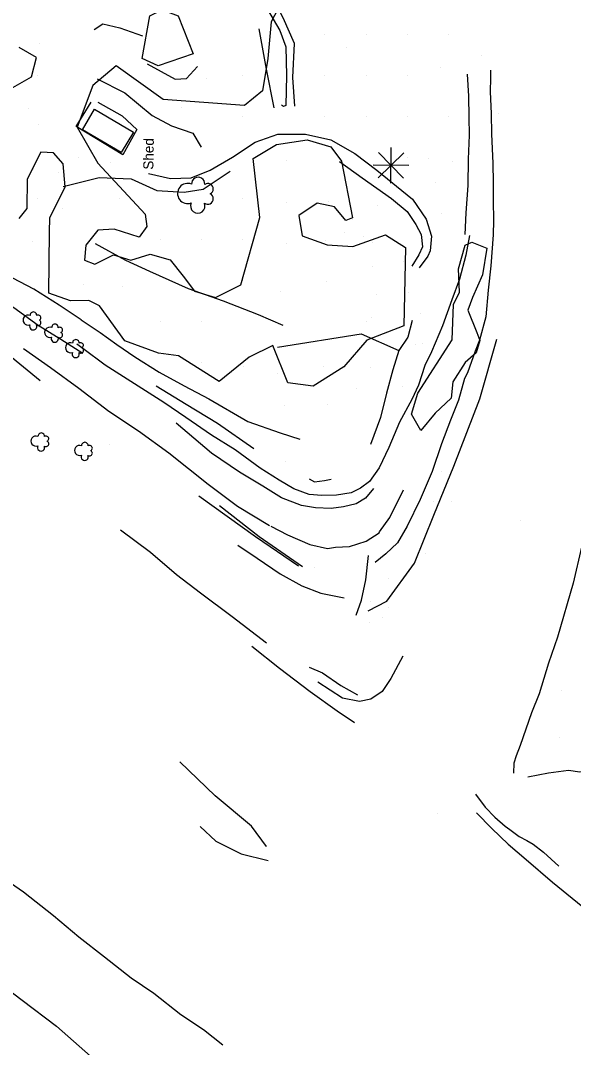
# Model space of a CAD drawing. Extents: x 19528164 to 19545171, y 7585743 to 7602745.
# Drawn here: x 19532177 to 19532446, y 7589871 to 7590372 of the extents above; entities that cross this region are included whole.
import ezdxf

# ---------------------------------------------------------------- set-up
doc = ezdxf.new("R2010")
doc.units = 0
for name, color, linetype in [('PhoBreakLine', 7, 'Continuous'), ('PhoBuilding', 7, 'Continuous'), ('PhoConcreteSlab', 7, 'Continuous'), ('PhoISAEPoints', 7, 'Continuous'), ('PhoNotesDesign', 7, 'Continuous'), ('PhoVegetation', 7, 'Continuous'), ('SurNaturalCells', 7, 'Continuous')]:
    doc.layers.add(name, color=color, linetype=linetype)

# ---------------------------------------------------------------- blocks, each defined once
blk = doc.blocks.new('TRDC')
at = {"layer": 'PhoVegetation'}
for centre, radius, start, end in [((-6, -1.1), 3.52, 65.4824, 294.5175), ((0.1, 4), 4.92, 338.2051, 201.7949), ((4.9, -1.1), 3.21, 265.9982, 94.0018), ((-2.4, -5.9), 2.68, 142.7501, 335.3223), ((2.5, -5.8), 2.67, 206.5242, 35.4033)]:
    blk.add_arc(centre, radius, start, end, dxfattribs=at)

msp = doc.modelspace()

# ---------------------------------------------------------------- linework, layer by layer
at = {"layer": 'PhoBreakLine'}
for points in [[(19532310.39, 7590329.98), (19532309.35, 7590344.06), (19532310.11, 7590360.5), (19532304.61, 7590373.08), (19532299.72, 7590382.39), (19532298.65, 7590391.57), (19532295.72, 7590394.62), (19532287.91, 7590398.6)], [(19532288.27, 7590393.6), (19532293.08, 7590389.87), (19532295.51, 7590383.77), (19532297.08, 7590377.09), (19532302.98, 7590366.85), (19532305.87, 7590359.01), (19532306.27, 7590344.88), (19532305.94, 7590330.27), (19532304.87, 7590329.92), (19532303.89, 7590330.48)], [(19531952.11, 7590377.89), (19531963.88, 7590371.42), (19531980.15, 7590359.08), (19531999.76, 7590345.93), (19532028.04, 7590328.79), (19532041.73, 7590318.4), (19532058.28, 7590306.88), (19532078.33, 7590292.93), (19532101.08, 7590277.81), (19532127.97, 7590259.07), (19532139.92, 7590252.05), (19532145.93, 7590249.55), (19532156.87, 7590241.46), (19532173.4, 7590231.88), (19532185.29, 7590223.17), (19532196.32, 7590216.45), (19532207.14, 7590209.52)], [(19532206.29, 7590225.89), (19532195.53, 7590233.02), (19532183.27, 7590240.78), (19532165.94, 7590249.69), (19532156.57, 7590255.2), (19532143.79, 7590261.17), (19532136.29, 7590268.64), (19532127.31, 7590273.77), (19532121.44, 7590279.07), (19532114.67, 7590283.35), (19532100.93, 7590291.18), (19532088.46, 7590299.14), (19532077.79, 7590306.95), (19532068.4, 7590313.63), (19532060.03, 7590319.64), (19532049.41, 7590325.62), (19532039.33, 7590332.99), (19532028.79, 7590340.47), (19532018.38, 7590349.36), (19532006.17, 7590358.14), (19531996.03, 7590365.75), (19531986.71, 7590372.87)], [(19532212.6, 7590367.34), (19532216.78, 7590370.08), (19532225.16, 7590368.28), (19532236.11, 7590364.37)], [(19532292.76, 7590367.65), (19532296.39, 7590348.02), (19532300.02, 7590329.24)], [(19532238.38, 7590350.63), (19532251.97, 7590343.19), (19532257.5, 7590343.55), (19532262.89, 7590349.29)], [(19532405.59, 7590347.54), (19532405.64, 7590343.9), (19532405.4, 7590336.97), (19532405.88, 7590326.38), (19532406.07, 7590316.34), (19532406.74, 7590302.26), (19532406.86, 7590292.57), (19532406.89, 7590284), (19532407.11, 7590274.27), (19532406.84, 7590267.32), (19532405.78, 7590252.1), (19532404.4, 7590240.37), (19532403.25, 7590227.29), (19532400.24, 7590215.93), (19532398.17, 7590210.58), (19532394.4, 7590200.02), (19532392.92, 7590197.29), (19532390.04, 7590186.74), (19532386.16, 7590176.95), (19532381.78, 7590165.36), (19532377.24, 7590151.87), (19532371.31, 7590138.22), (19532364.94, 7590125.18), (19532360.29, 7590117.08), (19532354.59, 7590111.78), (19532349.45, 7590107.53)], [(19532213.99, 7590343.3), (19532227.54, 7590336.47), (19532240.84, 7590325.39), (19532250.26, 7590320.41), (19532260.56, 7590316.89), (19532264.62, 7590310.08)], [(19532393.3, 7590267.39), (19532393.81, 7590277.95), (19532394.67, 7590291.33), (19532394.92, 7590304.11), (19532395.33, 7590315.93), (19532395.22, 7590324.68), (19532395.04, 7590334.84), (19532394.4, 7590345.65)], [(19532214.3, 7590332.01), (19532226.24, 7590325.28), (19532233.32, 7590318.62), (19532226.62, 7590306.36), (19532203.76, 7590320.1), (19532211.15, 7590331.94)], [(19532239.11, 7590297.2), (19532249.76, 7590294.81), (19532259.89, 7590295.05), (19532269.07, 7590298.83), (19532279.95, 7590305.11), (19532290.94, 7590312.38), (19532301.97, 7590316.33), (19532315.55, 7590316.4), (19532327.9, 7590313.58), (19532339.6, 7590306.93), (19532350.21, 7590298.78), (19532367.55, 7590284.75), (19532374.2, 7590274.98), (19532376.93, 7590266.58), (19532376.26, 7590259.54), (19532375.03, 7590256.82), (19532370.91, 7590251.13)], [(19532332.07, 7590303.06), (19532343.08, 7590295.05), (19532357.45, 7590285.03), (19532364.99, 7590278.66), (19532369.31, 7590272.26), (19532371.91, 7590267.41), (19532372.45, 7590261.45), (19532370.69, 7590257.61), (19532367.34, 7590251.96)], [(19532230.68, 7590294.57), (19532243.12, 7590288.95), (19532256.48, 7590288.07), (19532265.74, 7590289.47), (19532278.77, 7590298.38)], [(19532197.55, 7590290.83), (19532215.04, 7590295.29), (19532230.68, 7590294.57)], [(19532395.3, 7590266.96), (19532393.52, 7590257.31), (19532390.45, 7590245.72), (19532386.82, 7590235.67), (19532382.27, 7590222.85), (19532376.82, 7590210.32), (19532373.65, 7590203.61), (19532370.47, 7590194.04), (19532367.33, 7590186.93), (19532361.23, 7590175.91), (19532356.11, 7590163.68), (19532351.43, 7590153.77), (19532346.6, 7590147.02), (19532342.3, 7590143.7), (19532337.72, 7590141.47), (19532330.55, 7590140.31), (19532323.49, 7590140.15), (19532317.27, 7590140.61), (19532309.78, 7590143.53), (19532302.68, 7590147.66), (19532293.45, 7590153.52), (19532281.28, 7590162.39), (19532269.75, 7590169.59), (19532257.27, 7590178.17), (19532246.5, 7590185.51), (19532232.21, 7590194.72), (19532217.99, 7590203.76), (19532207.1, 7590211.86), (19532204.18, 7590213.9)], [(19532213.04, 7590263.05), (19532227.8, 7590254.88), (19532239.57, 7590249.55), (19532258.32, 7590241.11), (19532275.46, 7590235.1), (19532292.51, 7590228.47), (19532304.48, 7590223.29)], [(19532471.34, 7590252.36), (19532473.07, 7590240.9), (19532472.99, 7590225.89), (19532471.86, 7590210.37), (19532469.14, 7590193.18), (19532465.68, 7590174.46), (19532462.79, 7590158.1), (19532455.11, 7590131.24), (19532449.95, 7590114.96), (19532445.84, 7590097.49), (19532438.24, 7590071.21), (19532433.84, 7590058.48), (19532431.63, 7590050.93), (19532429.34, 7590043.46), (19532425.56, 7590034.27), (19532419.98, 7590018.25), (19532418.04, 7590013.36), (19532417.02, 7590009.67), (19532416.83, 7590004.81)], [(19532131.78, 7590239.08), (19532155.46, 7590221.38), (19532186.32, 7590196.34)], [(19532206.29, 7590225.89), (19532215.53, 7590219.69), (19532223.6, 7590213.89), (19532232.47, 7590207.87), (19532244.25, 7590200.41), (19532256.5, 7590193.6), (19532268.51, 7590187.35), (19532287.5, 7590176.36), (19532303.1, 7590170.78), (19532312.7, 7590167.7)], [(19532367.46, 7590225.6), (19532365.42, 7590217.4), (19532360.97, 7590210.96), (19532357.98, 7590201.42), (19532354.89, 7590190.03), (19532352.03, 7590178.22), (19532347.23, 7590165.08)], [(19532301.87, 7590212.56), (19532342.65, 7590219.02), (19532360.97, 7590210.96)], [(19532178.16, 7590211.87), (19532191.31, 7590202.56), (19532205.19, 7590192.55), (19532219.75, 7590181.32), (19532234.16, 7590171.76), (19532248.98, 7590160.95), (19532268.18, 7590145.7), (19532282.47, 7590135.07), (19532297.93, 7590125.5)], [(19532346.1, 7590083.95), (19532355.16, 7590088.64), (19532368.54, 7590107.25), (19532378.03, 7590130.54), (19532387.74, 7590154.46), (19532400.44, 7590187.4), (19532408.74, 7590216.36)], [(19532242.74, 7590193.61), (19532257.37, 7590184.68), (19532272.73, 7590175.41), (19532290.31, 7590163.09)], [(19532348.69, 7590143.59), (19532344.74, 7590138.98), (19532340.24, 7590136.06), (19532334, 7590134.61), (19532328.03, 7590133.89), (19532320.43, 7590134.18), (19532313.61, 7590135.38), (19532303.86, 7590139.08), (19532294.65, 7590144.68), (19532283.3, 7590151.64), (19532269.68, 7590160.86), (19532252.54, 7590175.4)], [(19532317.27, 7590148.37), (19532319.81, 7590146.81), (19532324.69, 7590147.44), (19532328.01, 7590148.21)], [(19532298.55, 7590125.23), (19532306.74, 7590121.05), (19532317.61, 7590116.34), (19532326.2, 7590114.42), (19532330.05, 7590115.09), (19532336.89, 7590115.28), (19532345.02, 7590117.91), (19532351.46, 7590122), (19532351.62, 7590122.55), (19532356.53, 7590129.42), (19532363.17, 7590142.96)], [(19532312.05, 7590105.69), (19532291.17, 7590120.12), (19532263.58, 7590139.95)], [(19532314.05, 7590105.39), (19532292.88, 7590120.11), (19532273.7, 7590135.15)], [(19532225.4, 7590123.51), (19532240, 7590112.62), (19532252.68, 7590101.68), (19532264.36, 7590092.76), (19532279.75, 7590081.24), (19532296.48, 7590068.31)], [(19532282.56, 7590116.07), (19532291.89, 7590109.69), (19532303.13, 7590102.08), (19532313.77, 7590096.15), (19532323.01, 7590092.52), (19532334.38, 7590090.38)], [(19532340.23, 7590081.81), (19532342.8, 7590089.23), (19532344.87, 7590099.07), (19532346.12, 7590110.99)], [(19531943.66, 7590093.23), (19531956.95, 7590083.75), (19531973.48, 7590072.16), (19531986.18, 7590061.94), (19531997.32, 7590054.52), (19532003.54, 7590049.96), (19532012.67, 7590041.24), (19532027.38, 7590026.9), (19532038.35, 7590015.15), (19532049.39, 7590006.69), (19532058.68, 7589999.2), (19532065.06, 7589990.64), (19532074.56, 7589979.59), (19532089.81, 7589967.19), (19532103.84, 7589955.23), (19532121.49, 7589938.61), (19532138.11, 7589923.71), (19532161.1, 7589906.46), (19532177.61, 7589894.18), (19532194.23, 7589881.57), (19532216.34, 7589861.94), (19532233.39, 7589846.76), (19532248.3, 7589832.75)], [(19532289.35, 7590066.7), (19532302.87, 7590056.09), (19532317.72, 7590044.64), (19532330.85, 7590035.19), (19532339.29, 7590029.61)], [(19532362.88, 7590061.95), (19532357.05, 7590050.92), (19532352.82, 7590044.71), (19532347.4, 7590040.91), (19532341.74, 7590039.75), (19532333.49, 7590041.36), (19532321.56, 7590049.18)], [(19532317.24, 7590056.48), (19532323.83, 7590053.77), (19532332.73, 7590047.58), (19532340.89, 7590043.05)], [(19532296.55, 7589969.02), (19532296.53, 7589969.09), (19532289.22, 7589978.93), (19532271.44, 7589993.73), (19532254.37, 7590010.31)], [(19532423.81, 7590003.1), (19532433.91, 7590005.02), (19532443.57, 7590006.27), (19532449.06, 7590005.46), (19532456.93, 7590006.98), (19532464.94, 7590008.3), (19532469.91, 7590009.48)], [(19532398.36, 7589994.57), (19532403.03, 7589988.26), (19532407.75, 7589983.39), (19532412.7, 7589978.96), (19532415.02, 7589977.33), (19532419.5, 7589974.01), (19532423.21, 7589972.07), (19532426.4, 7589970.29), (19532431.41, 7589966.27), (19532438.88, 7589959.53)], [(19532398.73, 7589985.55), (19532406.3, 7589977.89), (19532414.23, 7589970.19), (19532422.89, 7589962.79), (19532435.76, 7589951.77), (19532448.03, 7589941.8), (19532460.66, 7589931.47), (19532474.55, 7589920.17), (19532492.54, 7589904.91), (19532510.78, 7589889.47), (19532532.24, 7589872.05), (19532549.74, 7589859.48), (19532570.76, 7589842.62), (19532589.33, 7589827.72), (19532610.19, 7589811.03), (19532628.19, 7589795.74), (19532654.79, 7589774.06), (19532674.84, 7589758.75), (19532701.07, 7589737.17), (19532717.49, 7589723.97)], [(19532264.17, 7589978.88), (19532271.91, 7589971.73), (19532284.22, 7589965.54), (19532297.3, 7589962.3)], [(19532275.33, 7589872.22), (19532265.81, 7589879.73), (19532254.82, 7589887.09), (19532241.57, 7589897.37), (19532230.6, 7589904.88), (19532217.68, 7589915.18), (19532205.06, 7589924.82), (19532192.85, 7589935.31), (19532178.19, 7589946.82), (19532167.66, 7589954.09)]]:
    msp.add_lwpolyline(points, dxfattribs=at)
at = {"layer": 'PhoBuilding'}
msp.add_lwpolyline([(19532212.7, 7590328.5), (19532231.67, 7590317.36), (19532225.82, 7590307.38), (19532206.84, 7590318.52)], close=True, dxfattribs=at)
at = {"layer": 'PhoConcreteSlab'}
msp.add_lwpolyline([(19532239.7, 7590374), (19532245.71, 7590377.02), (19532253.56, 7590374), (19532260.84, 7590355.52), (19532243.84, 7590349.74), (19532236.01, 7590353.17)], close=True, dxfattribs=at)
at = {"layer": 'PhoISAEPoints'}
for p, q in [((19532325, 7590365), (19532325, 7590365)), ((19532345, 7590365), (19532345, 7590365)), ((19532365, 7590365), (19532365, 7590365)), ((19532385, 7590365), (19532385, 7590365)), ((19532186.21, 7590360.75), (19532186.21, 7590360.75)), ((19532335.35, 7590358.75), (19532335.35, 7590358.75)), ((19532401.13, 7590354.92), (19532401.13, 7590354.92)), ((19532381.41, 7590348.87), (19532381.41, 7590348.87)), ((19532185, 7590345), (19532185, 7590345)), ((19532267.4, 7590343.4), (19532267.4, 7590343.4)), ((19532285, 7590345), (19532285, 7590345)), ((19532325, 7590345), (19532325, 7590345)), ((19532345, 7590345), (19532345, 7590345)), ((19532365, 7590345), (19532365, 7590345)), ((19532180.65, 7590328.66), (19532180.65, 7590328.66)), ((19532255.13, 7590329.46), (19532255.13, 7590329.46)), ((19532285, 7590325), (19532285, 7590325)), ((19532325, 7590325), (19532325, 7590325)), ((19532345, 7590325), (19532345, 7590325)), ((19532365, 7590325), (19532365, 7590325)), ((19532385, 7590325), (19532385, 7590325)), ((19532409.4, 7590326.23), (19532409.4, 7590326.23)), ((19532185.64, 7590320.97), (19532185.64, 7590320.97)), ((19532190.92, 7590307.4), (19532190.92, 7590307.4)), ((19532205.04, 7590305.17), (19532205.04, 7590305.17)), ((19532212.16, 7590306.33), (19532212.16, 7590306.33)), ((19532220.51, 7590302.69), (19532220.51, 7590302.69)), ((19532306.34, 7590303.67), (19532306.34, 7590303.67)), ((19532365, 7590305), (19532365, 7590305)), ((19532375.53, 7590304.31), (19532375.53, 7590304.31)), ((19532386.85, 7590303.1), (19532386.85, 7590303.1)), ((19532183.17, 7590299), (19532183.17, 7590299)), ((19532195.29, 7590297.88), (19532195.29, 7590297.88)), ((19532378.58, 7590292.8), (19532378.58, 7590292.8)), ((19532185, 7590285), (19532185, 7590285)), ((19532225, 7590285), (19532225, 7590285)), ((19532285, 7590285), (19532285, 7590285)), ((19532306.09, 7590282.91), (19532306.09, 7590282.91)), ((19532326.49, 7590283.75), (19532326.49, 7590283.75)), ((19532350.67, 7590281.7), (19532350.67, 7590281.7)), ((19532197.17, 7590280.36), (19532197.17, 7590280.36)), ((19532381.89, 7590277.74), (19532381.89, 7590277.74)), ((19532338.17, 7590274.92), (19532338.17, 7590274.92)), ((19532334.55, 7590268.54), (19532334.55, 7590268.54)), ((19532182.67, 7590264.17), (19532182.67, 7590264.17)), ((19532245, 7590265), (19532245, 7590265)), ((19532265, 7590265), (19532265, 7590265)), ((19532285, 7590265), (19532285, 7590265)), ((19532306.07, 7590263.29), (19532306.07, 7590263.29)), ((19532325.39, 7590264.5), (19532325.39, 7590264.5)), ((19532343.61, 7590266.37), (19532343.61, 7590266.37)), ((19532348.21, 7590263.49), (19532348.21, 7590263.49)), ((19532348.24, 7590251.61), (19532348.24, 7590251.61)), ((19532363.19, 7590254.07), (19532363.19, 7590254.07)), ((19532207.16, 7590242.91), (19532207.16, 7590242.91)), ((19532226.34, 7590242.15), (19532226.34, 7590242.15)), ((19532285, 7590245), (19532285, 7590245)), ((19532325.89, 7590244.76), (19532325.89, 7590244.76)), ((19532303.35, 7590239.64), (19532303.35, 7590239.64)), ((19532349.92, 7590238.02), (19532349.92, 7590238.02)), ((19532365.53, 7590239.04), (19532365.53, 7590239.04)), ((19532347.86, 7590226.76), (19532347.86, 7590226.76)), ((19532245, 7590225), (19532245, 7590225)), ((19532265, 7590225), (19532265, 7590225)), ((19532345, 7590225), (19532345, 7590225)), ((19532368.94, 7590213.99), (19532368.94, 7590213.99)), ((19532372.54, 7590214.24), (19532372.54, 7590214.24)), ((19532265, 7590205), (19532265, 7590205)), ((19532285.37, 7590203.3), (19532285.37, 7590203.3)), ((19532324.09, 7590202.97), (19532324.09, 7590202.97)), ((19532347.03, 7590202.74), (19532347.03, 7590202.74)), ((19532301.72, 7590199.51), (19532301.72, 7590199.51)), ((19532340.52, 7590192.13), (19532340.52, 7590192.13)), ((19532362.68, 7590193.41), (19532362.68, 7590193.41)), ((19532305.5, 7590184), (19532305.5, 7590184)), ((19532326.02, 7590184.53), (19532326.02, 7590184.53)), ((19532220, 7590165), (19532220, 7590165)), ((19532305.81, 7590156.85), (19532305.81, 7590156.85)), ((19532381.95, 7590152.06), (19532381.95, 7590152.06)), ((19532377.68, 7590137.36), (19532377.68, 7590137.36)), ((19532386.43, 7590137.24), (19532386.43, 7590137.24)), ((19532420.29, 7590128.21), (19532420.29, 7590128.21)), ((19532374.13, 7590112.03), (19532374.13, 7590112.03)), ((19532320, 7590105), (19532320, 7590105)), ((19532355.91, 7590099.59), (19532355.91, 7590099.59)), ((19532347.36, 7590088.55), (19532347.36, 7590088.55)), ((19532356.11, 7590085.47), (19532356.11, 7590085.47)), ((19532346.63, 7590078.28), (19532346.63, 7590078.28)), ((19532352.98, 7590080.77), (19532352.98, 7590080.77)), ((19532440, 7590045), (19532440, 7590045)), ((19532439.11, 7590022.22), (19532439.11, 7590022.22)), ((19532380, 7589985), (19532380, 7589985))]:
    msp.add_line(p, q, dxfattribs=at)
at = {"layer": 'PhoVegetation'}
for p, q in [((19532363.4, 7590307.26), (19532350.84, 7590295.09)), ((19532363.21, 7590294.9), (19532351.04, 7590307.46)), ((19532356.98, 7590292.43), (19532357.26, 7590309.93)), ((19532365.87, 7590301.04), (19532348.38, 7590301.32)), ((19532357.12, 7590301.18), (19532357.12, 7590301.18))]:
    msp.add_line(p, q, dxfattribs=at)
for points in [[(19532307.09, 7590387.11), (19532298.72, 7590371.13), (19532297.21, 7590353.26), (19532294.57, 7590337.43), (19532285.72, 7590330.3), (19532246.27, 7590333.31), (19532223.31, 7590349.65), (19532211.93, 7590340.13), (19532204.37, 7590319.8), (19532214.42, 7590302.24), (19532237.36, 7590277.32), (19532238.17, 7590271.36), (19532234.49, 7590266.07), (19532222.33, 7590269.99), (19532214.35, 7590269.6), (19532208.56, 7590262.29), (19532207.84, 7590254.95), (19532212.96, 7590252.93), (19532221.94, 7590257.55), (19532230.42, 7590254.93), (19532239.93, 7590257.87), (19532249.59, 7590255.06), (19532255.98, 7590247.12), (19532261.46, 7590239.75), (19532271.69, 7590236.79), (19532284.06, 7590242.9), (19532293.3, 7590275.67), (19532290.02, 7590304.5), (19532301.42, 7590311.25), (19532316.29, 7590313.6), (19532327.8, 7590310.26), (19532332.98, 7590303.14), (19532338.47, 7590275.61), (19532335.16, 7590274.35), (19532329.56, 7590280.99), (19532321.12, 7590282.77), (19532312.25, 7590276.69), (19532313.9, 7590266.74), (19532326.01, 7590262.46), (19532338.55, 7590261.64), (19532354.39, 7590267.28), (19532364.14, 7590261.04), (19532363.42, 7590222.87), (19532345.36, 7590215.87), (19532334.14, 7590202.91), (19532319.25, 7590193.56), (19532306.83, 7590195.18), (19532299.66, 7590213.41), (19532288.06, 7590207.64), (19532273.54, 7590195.76), (19532253.62, 7590208.32), (19532243.96, 7590209.52), (19532227.5, 7590215.61), (19532215.11, 7590232.75), (19532210.05, 7590235.3), (19532201.03, 7590235.16), (19532190.46, 7590238.92), (19532190.9, 7590268.6), (19532191.01, 7590275.61), (19532198.43, 7590290.68), (19532197.56, 7590301.82), (19532192.77, 7590307.21), (19532186.55, 7590307.53), (19532179.96, 7590294.37), (19532179.87, 7590280.17), (19532175.96, 7590275.25)], [(19532170.64, 7590337.77), (19532182.06, 7590344.36), (19532184.59, 7590353.69), (19532176.15, 7590358.56)]]:
    msp.add_lwpolyline(points, dxfattribs=at)
msp.add_lwpolyline([(19532386.49, 7590187.67), (19532378.65, 7590180.28), (19532371.73, 7590171.97), (19532367.19, 7590179.79), (19532370.16, 7590190.02), (19532386.89, 7590216.02), (19532387.59, 7590233.4), (19532390.47, 7590239.34), (19532390.06, 7590250.69), (19532393.22, 7590262.23), (19532396.49, 7590263.71), (19532403.82, 7590260.72), (19532401.71, 7590247.77), (19532396.79, 7590236.77), (19532394.63, 7590230.5), (19532398.88, 7590219.62), (19532400.43, 7590215.76), (19532398.67, 7590209.75), (19532393.31, 7590205.11), (19532387.21, 7590195.66)], close=True, dxfattribs=at)
for centre, radius, start, end in [((19532258.12, 7590287.46), 4.92, 67.3012, 290.8911), ((19532263.22, 7590292.17), 3.21, 355.0943, 183.0979), ((19532267.93, 7590289.69), 2.67, 295.6203, 124.4995), ((19532267.92, 7590284.87), 2.68, 231.8463, 64.4185), ((19532263.05, 7590281.35), 3.52, 154.5785, 23.6137)]:
    msp.add_arc(centre, radius, start, end, dxfattribs=at)
at = {"layer": 'SurNaturalCells'}
msp.add_line((19532371.47, 7590228.86), (19532371.47, 7590228.88), dxfattribs=at)
msp.add_line((19532371.47, 7590228.86), (19532371.47, 7590228.88), dxfattribs=at)
msp.add_circle((19532371.47, 7590228.87), 0.00459, dxfattribs=at)

# ---------------------------------------------------------------- block references
at = {"layer": 'PhoVegetation', "xscale": 0.49999999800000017, "yscale": 0.49999999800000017, "rotation": 89.09614373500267}
for p in [(19532182.41, 7590225.66), (19532192.92, 7590219.68), (19532203.11, 7590212.17), (19532186.23, 7590166.63), (19532207.46, 7590162.08)]:
    msp.add_blockref('TRDC', p, dxfattribs=at)

# ---------------------------------------------------------------- texts
at = {"layer": 'PhoNotesDesign'}
msp.add_text('Shed', height=4.92, rotation=89.0961, dxfattribs=at).set_placement((19532241.41, 7590299.03))

doc.saveas('drawing.dxf')
